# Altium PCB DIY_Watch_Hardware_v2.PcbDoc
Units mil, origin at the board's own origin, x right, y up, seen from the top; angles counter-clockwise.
Board outline 2125.98 x 1181.1 mil, 2 copper layers (Top Layer, Bottom Layer); 60 components, 43 nets, 258 pads, 23 vias.
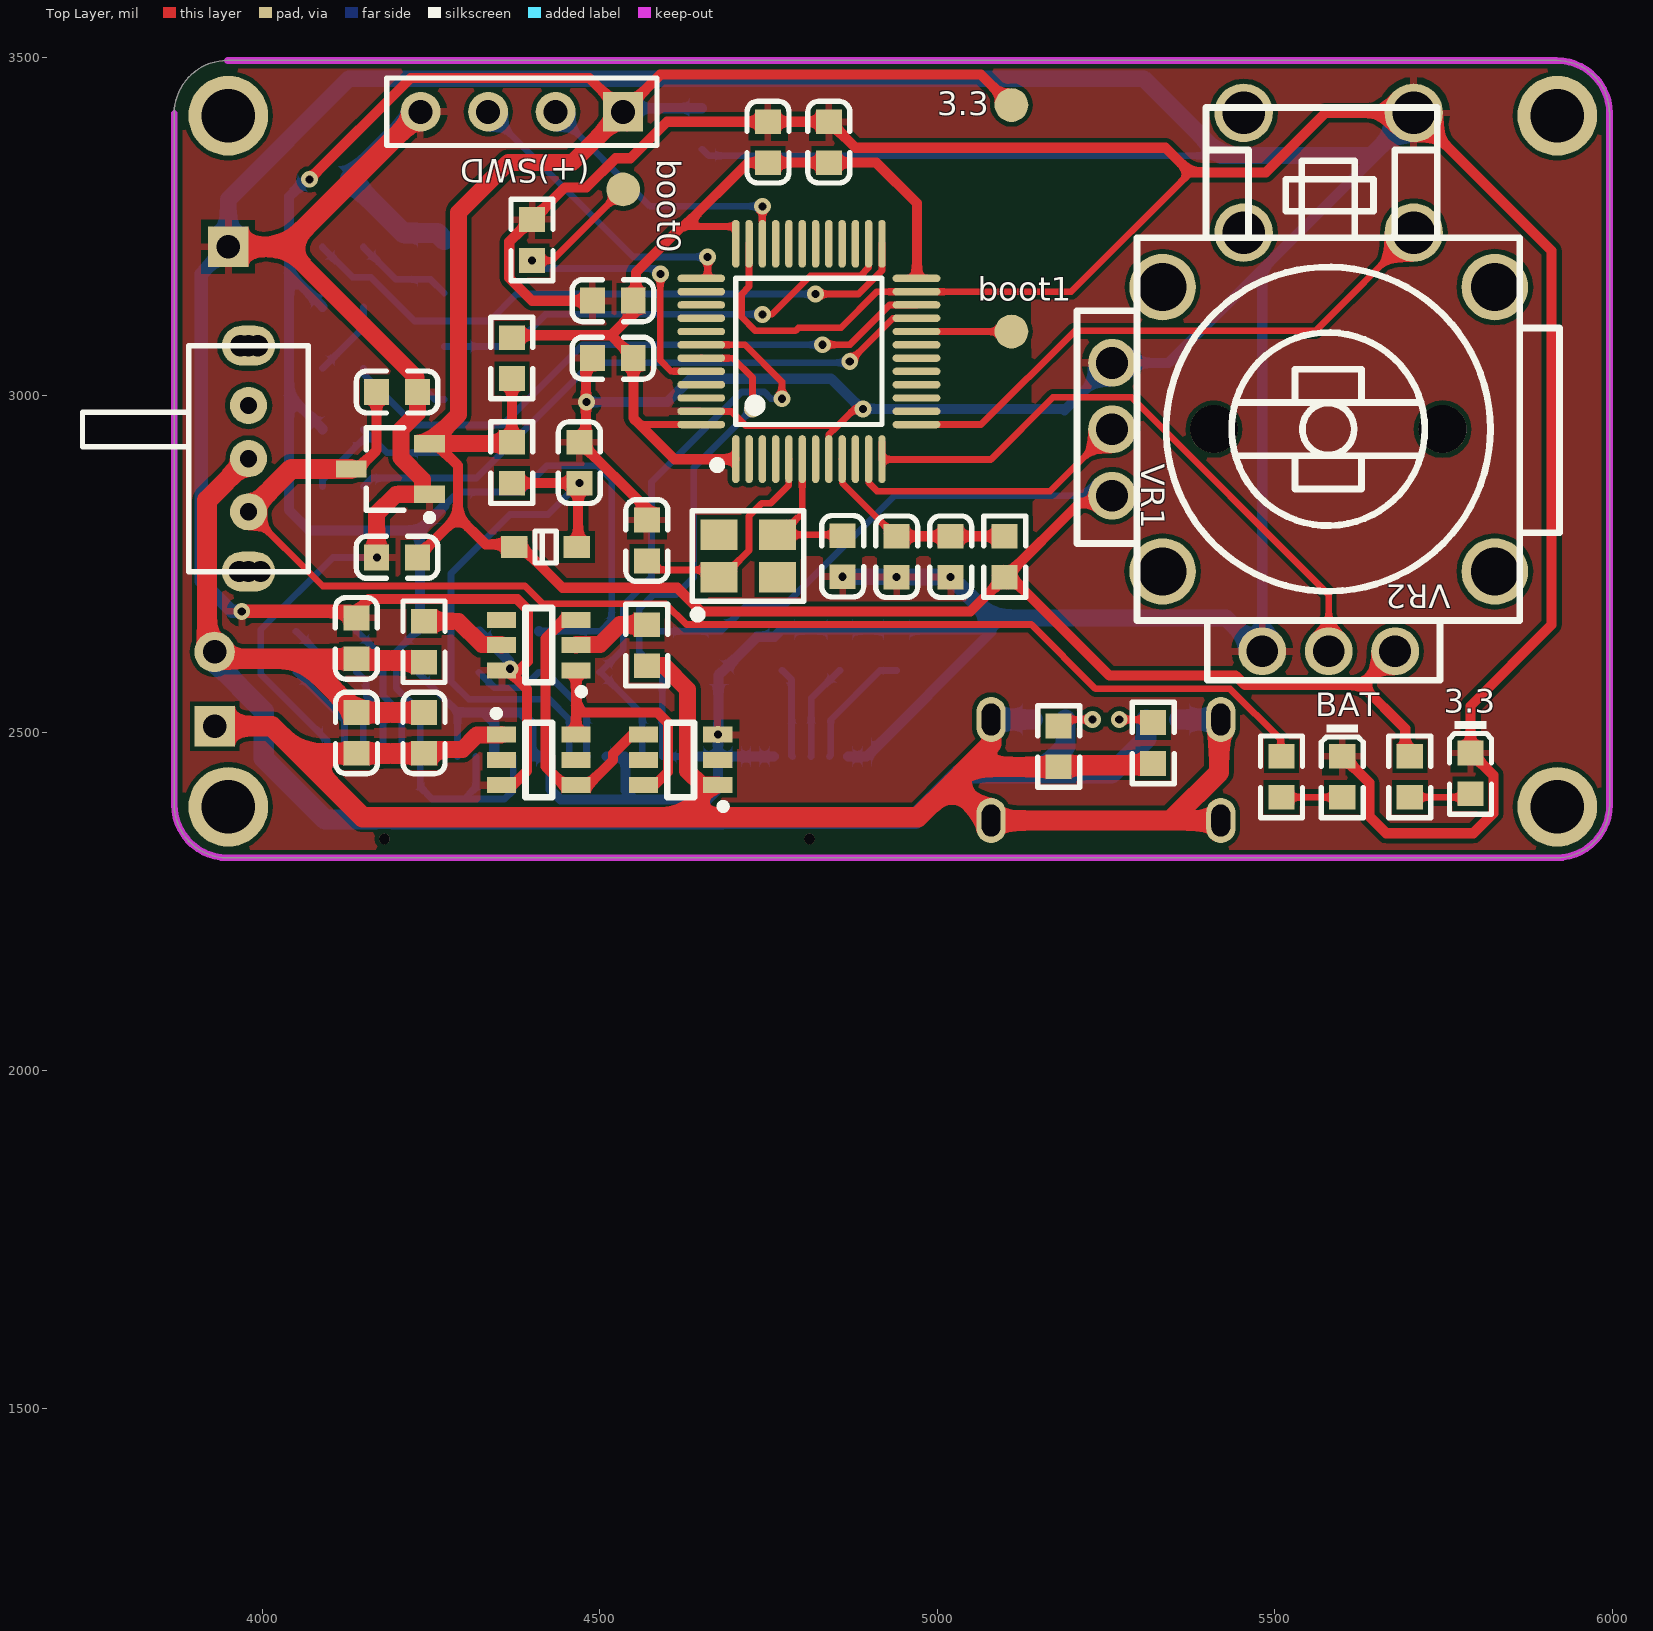
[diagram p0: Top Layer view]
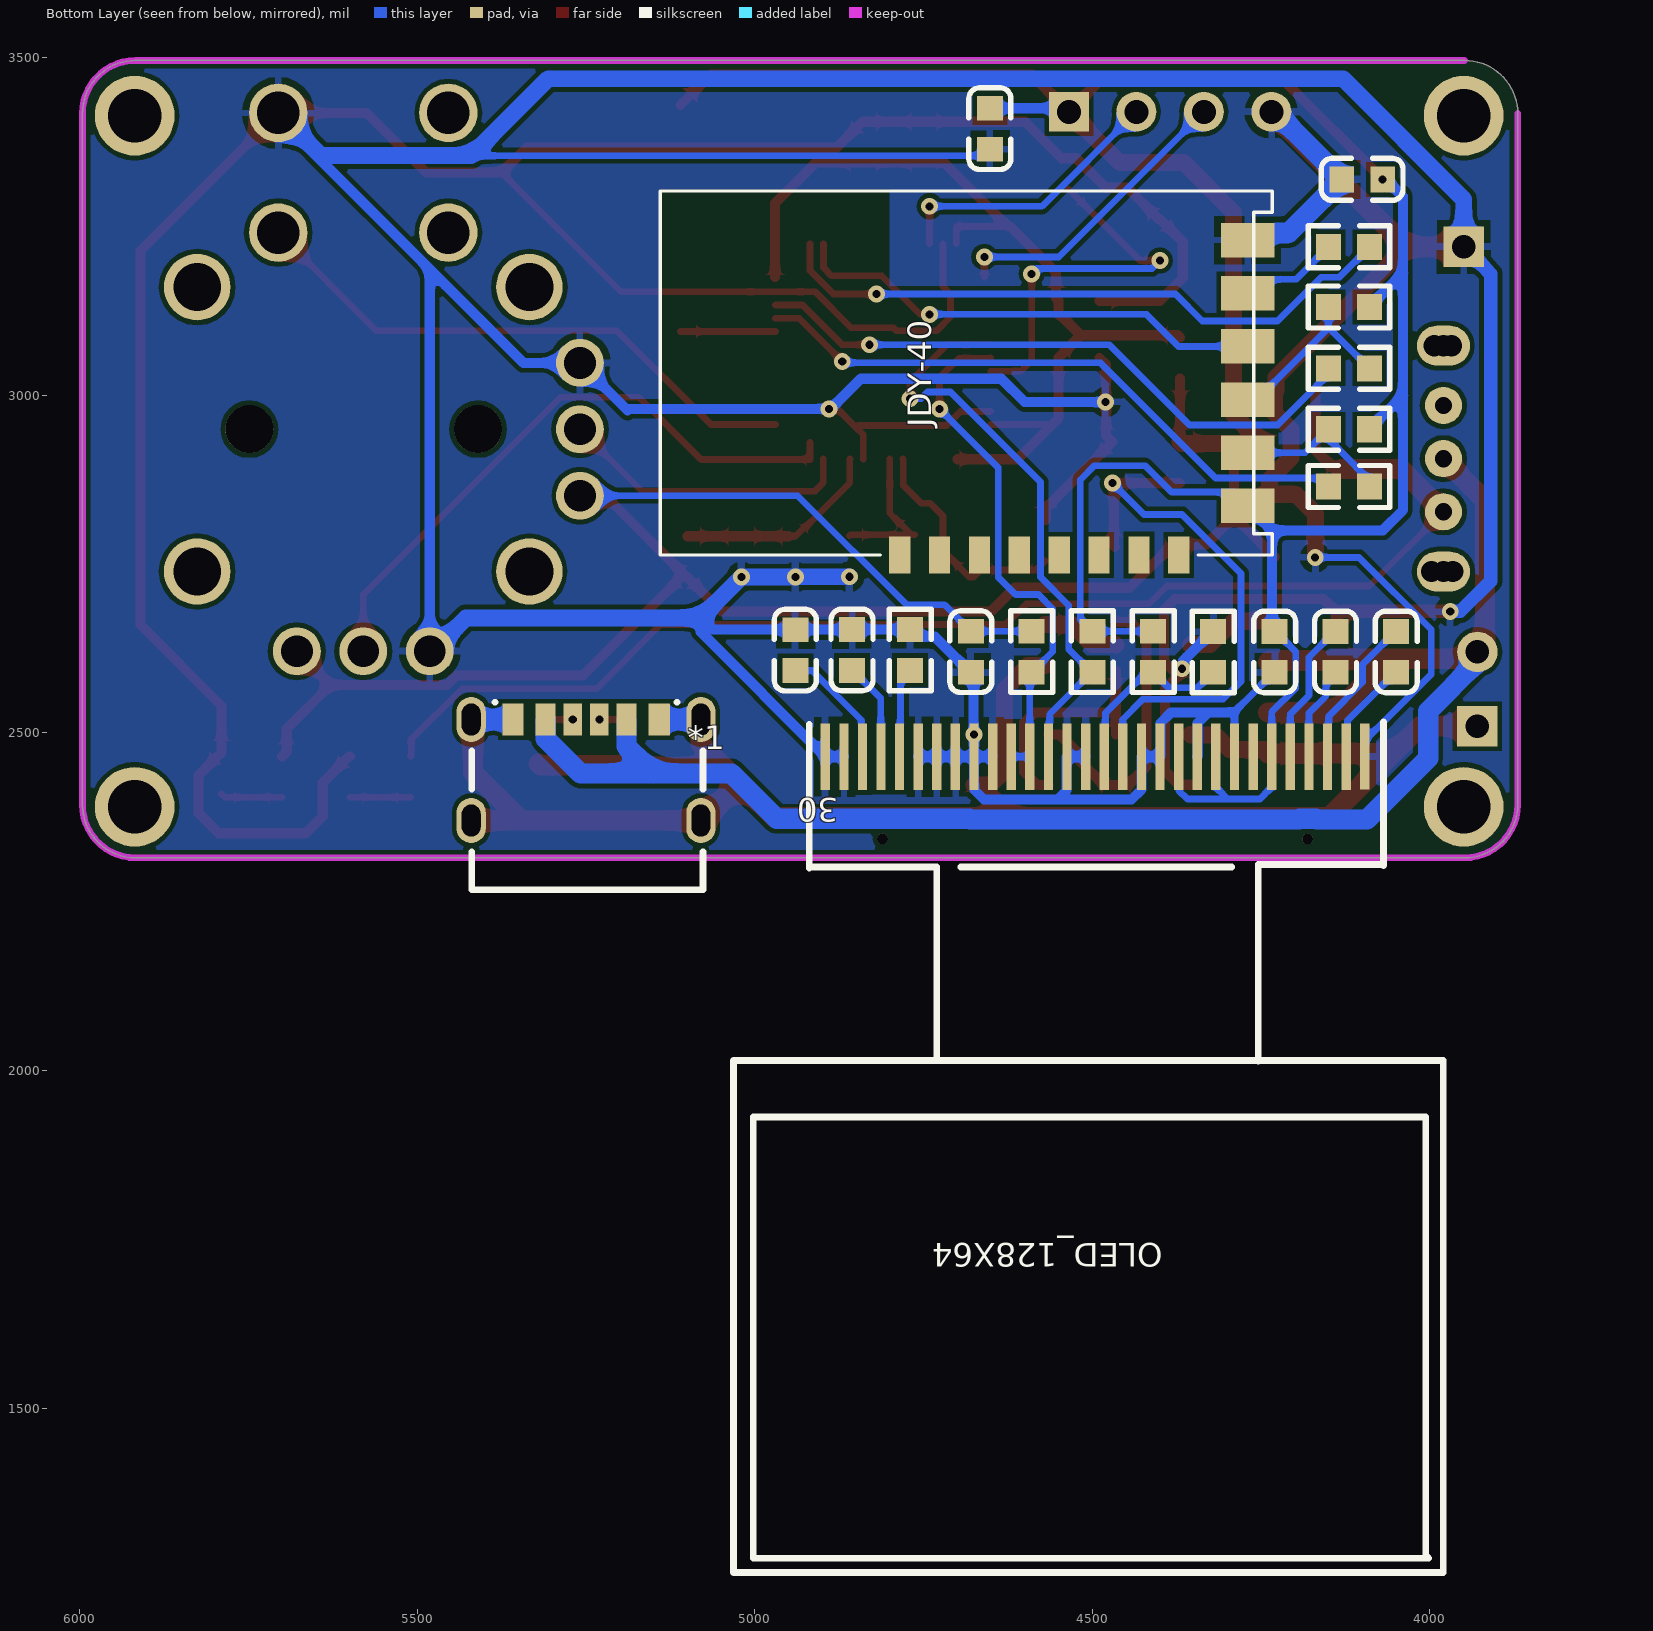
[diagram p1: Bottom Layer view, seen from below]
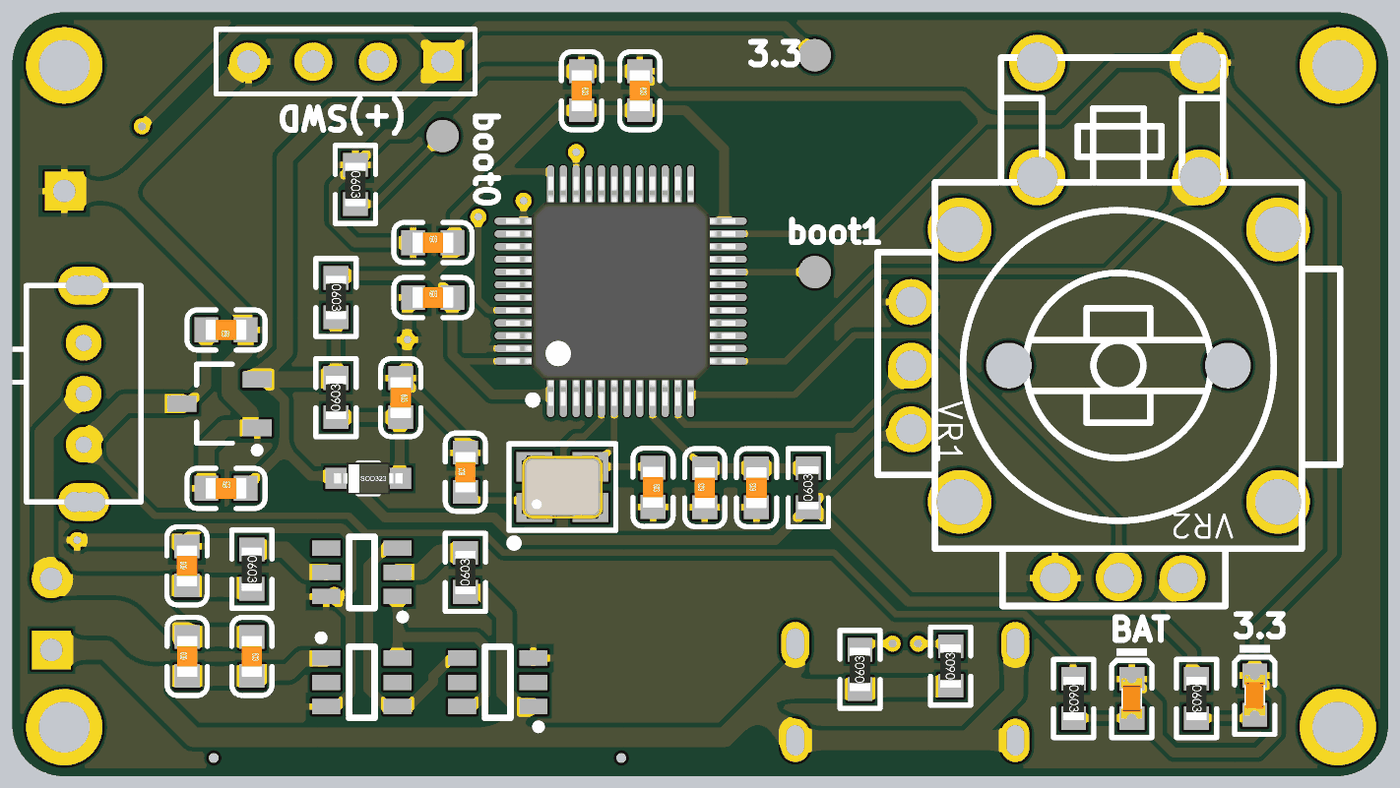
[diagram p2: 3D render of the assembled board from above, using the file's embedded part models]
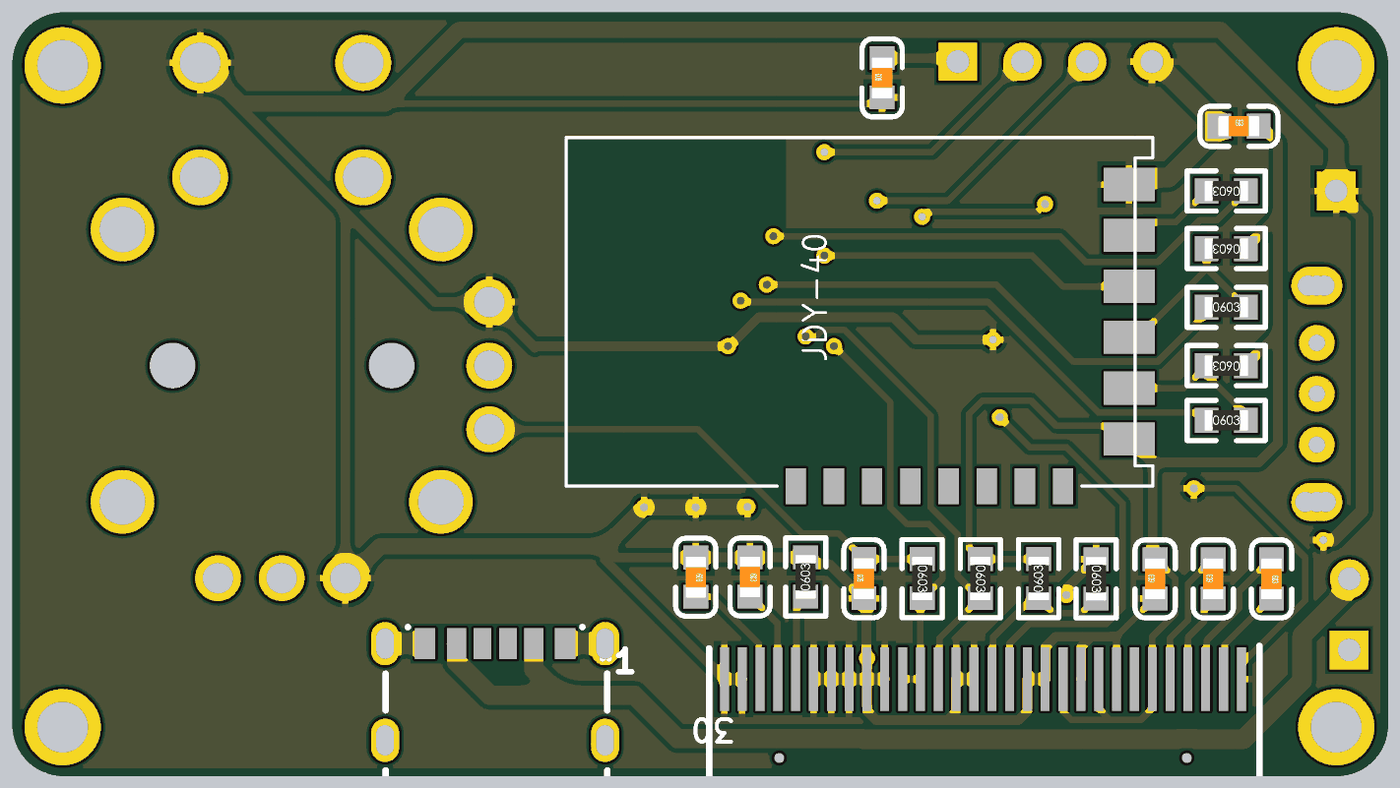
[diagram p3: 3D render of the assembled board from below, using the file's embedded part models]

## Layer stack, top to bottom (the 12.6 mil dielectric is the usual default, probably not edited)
Top Solder: solder mask 0.4, Solder Resist, Dk 3.5
Top Layer: signal copper 1.4
Dielectric 1: dielectric 12.6, FR-4, Dk 4.8
Bottom Layer: signal copper 1.4
Bottom Solder: solder mask 0.4, Solder Resist, Dk 3.5

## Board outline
3870,2393.74 3870,3417.36 cw(c3948.74,3417.36) 3948.74,3496.1 5917.24,3496.1 cw(c5917.24,3417.36) 5995.98,3417.36 5995.98,2393.74 cw(c5917.24,2393.74) 5917.24,2315 3948.74,2315 cw(c3948.74,2393.74)

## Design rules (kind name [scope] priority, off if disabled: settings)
Clearance [All] p1: gap=7 ignorepadtopadclearanceinfootprint=FALSE
MinimumSolderMaskSliver [All] p1: minsoldermaskwidth=0
PolygonConnect [All] p1: connectstyle=Relief reliefconductorwidth=10 reliefentries=4 polygonreliefangle="90 Angle" airgapwidth=10
RoutingVias [All] p1: holewidth=12 width=25 viastyle="Through Hole" minholewidth=12 minwidth=25 maxholewidth=25 maxwidth=50
SilkToSilkClearance [All] p1: silktosilkclearance=0
SilkToSolderMaskClearance [IsPad] p1: minsilkscreentomaskgap=0 clearancetoexposedcopper=TRUE
SolderMaskExpansion [All] p1: expansion=4
Width [All] p1: maxlimit=100 minlimit=7 preferedwidth=10
27 further rules are at their usual default settings.

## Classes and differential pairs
component class DIY_Watch_Hardware: *1

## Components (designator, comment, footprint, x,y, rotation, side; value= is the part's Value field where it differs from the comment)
3.3 "TestPoint" TestPoint 5110,3430 r180 top (schematic designator TP4)
3.3 "红灯 0603" LC-0603_LED_S1 5790,2440 r270 top (schematic designator D2)
(+)SWD "Header 4" HDR1X4 4534.88,3420 r180 top (schematic designator SWD)
*1 "OLED_30Pin" OLED_0.96-30P-P0.70-12864 4495.98,2464.99 r0 bottom
BAT "红灯 0603" LC-0603_LED_S1 5600,2435 r270 top (schematic designator D3)
boot0 "TestPoint" TestPoint 4534.88,3305 r90 top (schematic designator TP1)
boot1 "TestPoint" TestPoint 5110,3094.53 r90 top (schematic designator TP7)
C2 "1uF/0603/50V" LC-0603_C 4050,2620 r270 bottom
C3 "1uF/0603/50V" LC-0603_C 4140,2620 r90 bottom
C4 "22pF/0603/50V" LC-0603_C 4570,2785 r90 top
C5 "22pF/0603/50V" LC-0603_C 4860,2761.65 r270 top
C6 "100nF/0603/50V" LC-0603_C 4519.69,3055.16 r0 top
C7 "100nF/0603/50V" LC-0603_C 4749.53,3375 r270 top
C8 "100nF/0603/50V" LC-0603_C 4519.69,3140.16 r0 top
C9 "100nF/0603/50V" LC-0603_C 4839.53,3375 r270 top
C10 "2.2uF/0603/16V" LC-0603_C 4940,2622.6 r270 bottom
C11 "4.7uF/0603/16V" LC-0603_C 4856.06,2622.91 r270 bottom
C12 "100nF/0603/50V" LC-0603_C 5020,2760.98 r90 top
C13 "1uF/0603/50V" LC-0603_C 4940,2760.98 r90 top
C14 "100nF/0603/50V" LC-0603_C 4139.69,2640 r90 top
C15 "1uF/0603/50V" LC-0603_C 4200,3005 r180 top
C16 "1uF/0603/50V" LC-0603_C 4200,2760 r0 top
C17 "10uF/0603/10V" LC-0603_C 4470,2900.32 r270 top
C18 "1uF/0603/50V" LC-0603_C 4680,2620.32 r90 bottom
C19 "1uF/0603/50V" LC-0603_C 4230,2620 r90 bottom
C20 "100nF/0603/50V" LC-0603_C 4100.43,3320 r180 bottom
C21 "100nF/0603/50V" LC-0603_C 4240,2500 r270 top
C22 "1uF/0603/50V" LC-0603_C 4140,2500 r90 top
C23 "104" LC-0603_C 4651.81,3395 r90 bottom
CiZhu1 "600R/0603/5%" 0603_R 5100,2760.98 r90 top value=?
D1 "1N4148WS T4" LC-SOD-323 4420,2775.32 r0 top
R1 "5.1kΩ/0603/1%" LC-0603_R 5320,2485 r90 top
R2 "10KΩ/0603/1%" LC-0603_R 4400,3230 r270 top
R3 "4.7KΩ/0603/1%" LC-0603_R 4410,2620.31 r90 bottom
R4 "4.7KΩ/0603/1%" LC-0603_R 4321.1,2620 r270 bottom
R5 "4.7KΩ/0603/1%" LC-0603_R 4500,2620.32 r270 bottom
R6 "4.7KΩ/0603/1%" LC-0603_R 4590,2620.32 r270 bottom
R7 "0Ω/0603/1%" LC-0603_R 4370,3055.16 r270 top
R8 "1KΩ/0603/1%" LC-0603_R 4570,2630 r90 top
R9 "100Ω/0603/1%" LC-0603_R 4240,2635 r270 top
R10 "5.1kΩ/0603/1%" LC-0603_R 5180,2480 r90 top
R11 "4.7KΩ/0603/1%" LC-0603_R 4120,2949.74 r0 bottom
R13 "4.7KΩ/0603/1%" LC-0603_R 4120,3130.87 r0 bottom
R14 "4.7KΩ/0603/1%" LC-0603_R 4370,2900.32 r90 top
R15 "100Ω/0603/1%" LC-0603_R 4120,2865 r180 bottom
R16 "100Ω/0603/1%" LC-0603_R 4120,3040 r180 bottom
R17 "100Ω/0603/1%" LC-0603_R 4120,3220 r0 bottom
R18 "1MΩ/0603/1%" LC-0603_R 4770,2622.91 r90 bottom
R19 "1KΩ/0603/1%" LC-0603_R 5700,2435 r270 top
R20 "1KΩ/0603/1%" LC-0603_R 5510,2435 r270 top
S "SW-SPDT" 8.5*3.5_3P 3981.97,2906.26 r270 top
SW1 "RKJXV1224005" RKJXV1224005 5579.94,2949.74 r180 top
U1 "STM32F103C8T6" LQFP-48_7x7x05P 4810,3065 r0 top
U2 "DW01KA" SOT-23-6 4410,2630 r0 top
U3 "SC8205C" SOT-23-6 4410,2460 r180 top
U4 "SC8205C" SOT-23-6 4620,2460 r0 top
U5 "SC662K-3.3V" SOT-23-3L 4190,2890.98 r0 top
USB1 "TYPE-C 6P" TYPE-C-SMD_TYPE-C-6P 5250,2445 r180 bottom
X1 "无源贴片晶振" SMD-3225_4P 4720,2761.97 r0 top
Y1 "JDY-40_1" "JDY-401 -No via" 4785.42,2763.43 r90 bottom

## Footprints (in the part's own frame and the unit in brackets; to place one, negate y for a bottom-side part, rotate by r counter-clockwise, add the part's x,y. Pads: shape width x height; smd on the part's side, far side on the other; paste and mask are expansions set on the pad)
8.5*3.5_3P [mm]
  round 1.4 hole 0.65: 1(2,-0.05) 2(0,-0.05) 3(-2,-0.05)
  oval 1.5x2 hole 0.8: 4(-4.25,-0.05) 5(4.25,-0.05)
  round 0.8 hole 0.8: 18(-4.25,0.3) 19(-4.25,-0.35) 20(4.25,0.4) 21(4.25,-0.4)
  silkscreen extent -4.25,-6.3 4.25,2.2
0603_R [mm]
  rect 0.93x0.98 smd: 1(-0.77,0) 2(0.77,0)
  silkscreen extent -1.53,-0.79 1.54,0.79, body extent -0.85,-0.4 0.85,0.4, height 0.56
HDR1X4 [mm] "Connector; Header; 4 Position"
  rect 1.5x1.5 hole 0.9: 1(0,0)
  round 1.5 hole 0.9: 2(2.54,0) 3(5.08,0) 4(7.62,0)
  silkscreen extent -1.27,-1.27 8.89,1.27
"JDY-401 -No via" [mm] "串口透传"
  rect 1.4x0.8 smd: 1(0,0) 2(0,-1.5) 3(0,-3) 4(0,-4.5) 5(0,-6) 6(0,-7.5) 7(0,-9) 8(0,-10.5)
  rect 1.3x2 smd: 9(1.85,-13.092) 10(3.85,-13.092) 11(5.85,-13.092) 12(7.85,-13.092) 13(9.85,-13.092) 14(11.85,-13.092)
  silkscreen extent 0,-14.02 13.7,9.01
LC-0603_C [mm]
  rect 0.93x0.98 smd: 1(-0.77,0) 2(0.77,0)
  silkscreen extent -1.53,-0.79 1.54,0.79, body extent -0.8,-0.4 0.8,0.4, height 0.3
LC-0603_LED_S1 [mm]
  rect 0.93x0.98 smd: A(0.77,0) K(-0.77,0)
  silkscreen extent -1.98,-0.79 1.54,0.79, body extent -0.8,-0.4 0.8,0.4, height 0.6
LC-0603_R [mm]
  rect 0.93x0.98 smd: 1(-0.77,0) 2(0.77,0)
  silkscreen extent -1.53,-0.79 1.54,0.79, body extent -0.85,-0.4 0.85,0.4, height 0.56
LC-SOD-323 [mm]
  rect 1x0.83 smd: 1(1.18,0) 2(-1.18,0)
  silkscreen extent -0.4,-0.6 0.4,0.6, body extent -1.35,-0.62 1.35,0.62, height 1.1
LQFP-48_7x7x05P [mm]
  oval 0.28x1.8 smd mask+0.051: 1(-2.75,-4.05) 2(-2.25,-4.05) 3(-1.75,-4.05) 4(-1.25,-4.05) 5(-0.75,-4.05) 6(-0.25,-4.05) 7(0.25,-4.05) 8(0.75,-4.05) 9(1.25,-4.05) 10(1.75,-4.05) 11(2.25,-4.05) 12(2.75,-4.05) 25(2.75,4.05) 26(2.25,4.05) 27(1.75,4.05) 28(1.25,4.05) 29(0.75,4.05) 30(0.25,4.05) 31(-0.25,4.05) 32(-0.75,4.05) 33(-1.25,4.05) 34(-1.75,4.05) 35(-2.25,4.05) 36(-2.75,4.05)
  oval 1.8x0.28 smd mask+0.051: 13(4.05,-2.75) 14(4.05,-2.25) 15(4.05,-1.75) 16(4.05,-1.25) 17(4.05,-0.75) 18(4.05,-0.25) 19(4.05,0.25) 20(4.05,0.75) 21(4.05,1.25) 22(4.05,1.75) 23(4.05,2.25) 24(4.05,2.75) 37(-4.05,2.75) 38(-4.05,2.25) 39(-4.05,1.75) 40(-4.05,1.25) 41(-4.05,0.75) 42(-4.05,0.25) 43(-4.05,-0.25) 44(-4.05,-0.75) 45(-4.05,-1.25) 46(-4.05,-1.75) 47(-4.05,-2.25) 48(-4.05,-2.75)
  silkscreen extent -3.6,-4.42 2.75,2.75, body extent -4.5,-4.5 4.5,4.5, height 1.6
OLED_0.96-30P-P0.70-12864 [mm]
  rect 0.351x2.499 smd: 1(-10.149,-0.002) 2(-9.444,0) 3(-8.744,0) 4(-8.044,0) 5(-7.344,0) 6(-6.644,0) 7(-5.944,0) 8(-5.244,0) 9(-4.544,0) 10(-3.844,0) 11(-3.144,0) 12(-2.444,0) 13(-1.744,0) 14(-1.044,0) 15(-0.344,0) 16(0.356,0) 17(1.056,0) 18(1.756,0) 19(2.456,0) 20(3.156,0) 21(3.856,0) 22(4.556,0) 23(5.256,0) 24(5.956,0) 25(6.656,0) 26(7.356,0) 27(8.056,0) 28(8.751,0.001) 29(9.45,0.002) 30(10.149,0.002)
  round 0.4 hole 0.4 unplated: ""(-8,3.1) ""(8,3.1)
  silkscreen extent -13.1,-1.3 13.6,30.7
RKJXV1224005 [mm]
  round 1.8 hole 1.2: 1(8.15,-2.5) 2(8.15,0) 3(8.15,2.5) 4(2.5,8.35) 5(0,8.35) 6(-2.5,8.35)
  round 2.5 hole 1.8: 7(-6.25,5.35) 8(-6.25,-5.35) 9(6.25,-5.35) 10(6.25,5.35)
  round 2.2 hole 1.6: a(-3.2,-7.4) b(-3.2,-11.9) c(3.2,-7.4) d(3.2,-11.9)
  round 1.8 hole 1.8 unplated: ""(-4.284,-0.006) ""(4.316,-0.006)
  silkscreen extent -8.68,-12.11 9.47,9.44
SMD-3225_4P [mm] "晶振"
  rect 1.4x1.15 smd: 1(-1.1,-0.8) 2(1.1,-0.8) 3(1.1,0.8) 4(-1.1,0.8)
  silkscreen extent -2.1,-2.35 2.1,1.7, body extent -1.6,-1.25 1.6,1.25, height 0.61
SOT-23-3L [mm] "http://www.aosmd.com/res/packaging_information/SOT-23-3L.pdf"
  rect 1.15x0.65 smd: 1(1.475,-0.95) 2(1.475,0.95) 3(-1.475,0)
  silkscreen extent -0.9,-1.95 1.6,1.55, body extent -0.9,-1.55 0.9,1.55, height 1.25
SOT-23-6 [mm]
  rect 1.1x0.6 smd: 1(1.4,-0.95) 2(1.4,0) 3(1.4,0.95) 4(-1.4,0.95) 5(-1.4,0) 6(-1.4,-0.95)
  silkscreen extent -0.5,-1.87 1.73,1.4
TestPoint [mil]
  round 50 smd: 1(0,0)
TYPE-C-SMD_TYPE-C-6P [mm]
  oval 1.1x1.7 hole 0.7 slot 1.2 at 90 deg: 7(-4.32,-1.9) 7(-4.32,1.9) 7(4.32,-1.9) 7(4.32,1.9)
  rect 0.7x1.2 smd: A5(-0.5,1.9) B5(0.5,1.9)
  rect 0.76x1.2 smd: A9(1.52,1.9) B9(-1.52,1.9)
  rect 0.8x1.2 smd: A12(2.75,1.9) B12(-2.75,1.9)
  silkscreen extent -4.3,-4.5 4.4,2.55

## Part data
3.3 BAT: library part "0603 红灯", "发光二极管", Package=0603, SuppliersPartNumber=C2286
(+)SWD: "Header, 4-Pin"
C2 C3 C13 C15 C16 C18 C19 C22: library part "0603 1uF (105) 10% 50V", "贴片电容", Package=0603, SuppliersPartNumber=C15849
C4 C5: library part "0603 22pF (220) 5% 50V", "贴片电容", Package=0603, SuppliersPartNumber=C1653
C6 C7 C8 C9 C12 C14 C20 C21: library part "0603 100nF (104) 10% 50V", "贴片电容", Package=0603, SuppliersPartNumber=C14663
C10: library part "0603 2.2uF (225) 10% 16V", "贴片电容", Package=0603, SuppliersPartNumber=C23630
C11: library part "0603 4.7uF (475) 10% 16V", "贴片电容", Package=0603, SuppliersPartNumber=C19666
C17: library part "0603 10uF (106) 10% 10V", "贴片电容", Package=0603, SuppliersPartNumber=C19702
C23: library part "Cap Chip 0603", "Polarized Capacitor (Radial)"
CiZhu1: library part Cizhu, "电阻_磁珠"
D1: library part "SOD-323 1N4148WS T4", "二极管", Package=SOD-323, SuppliersPartNumber=C2128
R1 R9 R10 R15 R16 R17: library part "0603 100Ω (1000) 1%", "贴片电阻", Package=0603, SuppliersPartNumber=C22775
R2: library part "0603 10KΩ (1002) 1%", "贴片电阻", Package=0603, SuppliersPartNumber=C25804
R3 R4 R5 R6 R11 R13 R14: library part "0603 4.7KΩ (4701) 1%", "贴片电阻", Package=0603, SuppliersPartNumber=C23162
R7: library part "0603 0Ω (0R0) 1%", "贴片电阻", Package=0603, SuppliersPartNumber=C21189
R8 R19 R20: library part "0603 1KΩ (1001) 1%", "贴片电阻", Package=0603, SuppliersPartNumber=C21190
R18: library part "0603 1MΩ (1004) 1%", "贴片电阻", Package=0603, SuppliersPartNumber=C22935
S: "SPDT Subminiature Toggle Switch, Right Angle Mounting, Vertical Actuation"
SW1: BOM_JLCPCB Part Class="Extended Part", BOM_Manufacturer="ALPS Electric"
U1: "ARM", Package=LQFP-48_7x7x05P, SuppliersPartNumber=C8734
U2: "锂电池保护芯片"
U3 U4: "二合一MOS"
U5: "LDO"
USB1: BOM_JLCPCB Part Class="Extended Part", BOM_Manufacturer="SHOU HAN"
X1: library part XTAL_4, "25M/3225"
Y1: "串口透传无过孔"

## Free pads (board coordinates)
  round 60 hole 35: 4(3929.68,2620)
  rect 60x60 hole 35: 5(3930,2510) 6(3950,3220)
  round 118.11 hole 78.74: 7(3950,2390.55) 7(3950,3414.17) 7(5918.5,2390.55) 7(5918.5,3414.17)

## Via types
v1: diameter 25, hole 12, Top Layer to Bottom Layer, 23 vias

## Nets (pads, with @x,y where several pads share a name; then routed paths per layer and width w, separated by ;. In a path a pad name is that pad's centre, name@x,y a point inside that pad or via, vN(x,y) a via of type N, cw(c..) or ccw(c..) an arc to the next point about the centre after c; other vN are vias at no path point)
3V3: 3.3.1 (+)SWD.1 *1.6 *1.9 *1.11 C16.2 C18.2 C19.2 C20.2 C23.2 CiZhu1.1 D1.2 R3.2 R5.1 R6.1 R7.2 R11.1 R13.1 R14.2 R19.1 SW1.3 SW1.6 U5.2 Y1.9 | length 7207.6
  Top Layer w15: v1(4070.11,3320) 4220.11,3470 4484.88,3470 4534.88,3420 4589.88,3475 5065,3475 3.3.1 ; C16.2 4230.31,2760.98 4290,2820.67 ; U5.2@4257.91,2928.39 4290,2896.3 4290,2820.67 ; R14.2 R7.2 ; SW1.3 5248.38,2840.63 5210.95,2840.63 CiZhu1.1@5100.98,2730.67 ; SW1.6 5628.43,2571.07 ; R19.1 5693.38,2471.94 5693.38,2506.12 5628.43,2571.07 ; 4290,2820.67 4331.36,2779.31 4369.55,2779.31 D1.2 4384.69,2775.32 4445,2715 4615,2715 4650,2680 5049.33,2680 CiZhu1.1 CiZhu1.1@5100.98,2730.67 ; CiZhu1.1@5100.98,2730.67 5109.33,2730.67 5255.23,2584.77 5442.1,2584.77 5455.79,2571.07 5628.43,2571.07
  Top Layer w25: U5.2 4257.91,2928.39 U5.2@4258.21,2928.68 ; R14.2 4368.05,2928.68 U5.2@4258.21,2928.68 ; 4534.88,3420 4459.57,3344.68 4364.69,3344.68 4290.98,3270.98 4290.98,2971.3 4258.21,2938.52 U5.2@4258.21,2928.68
  Bottom Layer w10: C19.2@4229.02,2650.32 4198.71,2620.01 4198.71,2566.41 4234.41,2530.71 *1.6 4234.41,2419.49 4251.9,2402 4299.59,2402 ; Y1.9 4290.59,2856.85 4382.94,2856.85 4421.94,2895.86 4497.03,2895.86 4517.89,2875 4517.89,2667.54 4500.98,2650.63 R5.1 R3.2 ; *1.9 4317.08,2419.49 4299.59,2402 ; *1.11 4372.2,2414.93 4359.27,2402 4299.59,2402 ; R6.1 C18.2 4719.37,2690 4775.55,2690 4936.87,2851.32 SW1.3
  Bottom Layer w15: v1(4070.11,3320) 4065.43,3320 4040,3294.57 4040,3181.54 ; R11.1 4089.69,2950.73 4040,3000.41 ; R13.1 4089.69,3131.85 4040,3181.54 ; C19.2@4229.02,2650.32 4233.74,2655.04 4233.74,2800 ; Y1.9 4233.74,2800 ; 4534.88,3420 4540.2,3425.32 C23.2 ; 4040,3000.41 4040,3181.54 ; 4040,3000.41 4040,2830 4070,2800 4233.74,2800
BAT: C14.1 C21.1 C22.2 pad.4 R9.2 S.2 USB1.A9 USB1.B9 | length 2556.1
  Top Layer w30: S.2@3976.26,2910 3976.26,2902.52 3918.63,2844.89 3918.63,2631.05 pad.4 3937.8,2620 3948.12,2609.68 4059.65,2609.68 ; C21.1 C22.2 4139.02,2530.32 4059.65,2609.68 ; R9.2 4237.5,2607.18 4142.19,2607.18 C14.1 4059.65,2609.68
  Bottom Layer w30: pad.4 3929.68,2605.32 4002.71,2532.29 4002.71,2462.29 4093.2,2371.8 4167.63,2371.8 4168.65,2372.81 4193.39,2372.81 4194.41,2371.8 4681.27,2371.8 4682.28,2372.81 4967.81,2372.81 5035,2440 5150,2440 ; USB1.A9 5190.12,2519.77 5190.12,2480.12 5150,2440 ; USB1.B9 USB1.B9 5309.8,2491.41 5258.39,2440 5150,2440
BAT+: C15.2 R20.1 S.1 U5.3 | length 2008.3
  Top Layer w10: S.1 4089.9,2717.62 4389.6,2717.62 4416.01,2691.21 4597.84,2691.21 4628.56,2660.5 5139.5,2660.5 5234.73,2565.27 5434.02,2565.27 5509.02,2490.27 5509.02,2465.31 R20.1
  Top Layer w15: U5.3 4141.77,2890.98 4169.69,2918.9 C15.2
  Top Layer w30: S.1 4043.46,2890.98 U5.3
BOOT0: boot0.1 R2.2 U1.44 | length 572.3
  Top Layer w10: v1(4400,3199.68) 4429.57,3199.68 boot0.1 ; v1(4590,3180) 4590,3051.53 4605.86,3035.67 4650.36,3035.67 U1.44
  Bottom Layer w10: v1(4400,3199.68) 4411.68,3188 4582,3188 v1(4590,3180)
BOOT1: boot1.1 U1.20 | length 140.6
  Top Layer w10: U1.20 boot1.1
CS: R17.1 U1.25 | length 945.2
  Top Layer w10: v1(4820,3150) 4883.39,3150 4918.27,3184.88 U1.25
  Bottom Layer w10: R17.1 4089.69,3219.02 4133.7,3175 4160.75,3175 4225.68,3110.07 4337.25,3110.07 4377.18,3150 v1(4820,3150)
GND: 3.3.K (+)SWD.4 *1.1 *1.8 *1.10 *1.12 *1.13 *1.16 *1.17 *1.21 *1.22 *1.23 *1.24 *1.25 *1.29 *1.30 BAT.K C4.2 C5.2 C6.1 C7.1 C8.1 C9.1 C10.1 C11.1 C12.1 C13.1 C14.2 C15.1 C16.1 C17.1 C18.1 C19.1 C20.1 C23.1 pad.6 R2.1 R4.1 R18.2 SW1.1 SW1.4 SW1.b U1.8 U1.23 U1.35 U1.47 U2.6 U3.3 U4.3 U5.1 Y1.14 | length 15123.5
  Top Layer w10: U1.47 4650.75,2976.22 4695.49,2976.22 4716.21,2955.5 4846.8,2955.5 4850,2952.3 ; U1.35 4721.42,3161.06 4710,3149.64 4710,3116.45 4730.95,3095.5 4789.9,3095.5 4794.51,3100.12 4857.55,3100.12 4911.01,3153.58 U1.23 5198.58,3153.58 5375,3330 ; U1.8 4839.33,2905.75 4839.33,2941.63 4850,2952.3 ; v1(4890,2980) 4877.7,2980 4850,2952.3
  Top Layer w15: C14.2@4130,2680 C14.2 4139.69,2680.33 4157.47,2698.12 4378.13,2698.12 4393.7,2682.56 4393.7,2605.7 4380.6,2592.6 ; U3.3 4355.57,2423.29 4372.14,2423.29 4392.22,2443.37 4392.22,2565.1 U2.6@4364.79,2592.53 ; C6.1 4479.69,3045.47 4479.69,2940.32 C17.1 4470.98,2930.63 4569.02,2832.6 4569.02,2815.32 C4.2 ; C8.1 4399.84,3140.16 4366.21,3173.79 4366.21,3227.51 4399.02,3260.31 R2.1 4400.98,3260.31 4448.57,3307.9 4480.41,3307.9 4523.71,3351.21 4545.65,3351.21 4599.76,3405.32 C7.1 C9.1 4840.51,3405.32 4879.07,3366.76 5338.24,3366.76 5375,3330 5486.65,3330 5574.89,3418.25 SW1.b 5910,3214.17 5910,2660 5790,2540 3.3.K 5790.98,2470.31 5823.79,2437.51 5823.79,2380.89 5794.23,2351.33 5665,2351.33 5640,2376.33 5640,2426.3 5600.98,2465.31 BAT.K
  Top Layer w20: v1(3970,2680) C14.2@4130,2680
  Top Layer w25: 4034.88,3220 4228.21,3026.67 4228.21,3007.11 C15.1 4230.31,2973.64 4205.93,2949.26 4205.93,2907.51 4237.93,2875.51 4237.93,2853.88 4238.23,2853.58 U5.1 4247.78,2853.29 4198.4,2853.29 4169.69,2824.57 C16.1
  Top Layer w30: pad.6 4034.88,3220 4234.88,3420
  Bottom Layer w10: *1.1 4096.41,2488.71 3997.92,2587.19 3997.92,2652.81 4105.12,2760 v1(4170,2760) ; C19.1 4230.98,2589.68 4289.52,2531.15 *1.8 ; C23.1 4661.49,3355 5420,3355
  Bottom Layer w15: 4289.52,2531.15 4297.49,2531.15 4298.14,2530.5 4328.19,2530.5 ; R4.1 4322.08,2650.31 4365.35,2607.05 4365.35,2596.91 v1(4367.27,2595) ; *1.10 4344.04,2465.6 4344.04,2514.65 4328.19,2530.5 ; v1(4480.54,2990) 4600.41,2990 4634.91,3024.5 4842.96,3024.5 4887.46,2980 v1(4890,2980) 5185.91,2980 5188.41,2977.51 SW1.1 5342.79,3048.17 5481.51,3186.89 ; *1.16 *1.17 4538.16,2464.4 4538.16,2414.47 4551.34,2401.3 ; *1.21 *1.22 ; *1.25 *1.24 *1.23 *1.22 ; *1.29 *1.30 5080.27,2649.62 5080.27,2670.4 5062.78,2652.91 C10.1 4939.84,2653.07 4856.22,2653.07 C11.1 R18.2 4759.19,2642.42 4733.41,2642.42 4680.98,2590 C18.1 4675.95,2585.95 4675.95,2506.7 4675.35,2506.1 *1.22 ; SW1.4 5481.51,3186.89 ; SW1.b 5705.92,3411.3 5481.51,3186.89 ; 4328.19,2530.5 4383.31,2530.5 4399.16,2514.65 4399.16,2465.6 *1.12 *1.13 4427.32,2415.95 4441.97,2401.3 4551.34,2401.3 ; 4551.34,2401.3 4660.7,2401.3 4674.75,2415.35 4674.75,2423.3 4675.35,2423.9 *1.22
  Bottom Layer w20: pad.6 3910,3180 3910,2725 3955,2680 v1(3970,2680)
  Bottom Layer w25: pad.6 3950,3290 4129.03,3469.03 5305.97,3469.03 5420,3355 5642.67,3355 SW1.b ; v1(4860,2731.34) 4939.33,2731.34 v1(4940,2730.67) v1(5020,2730.67) 5080.27,2670.4 5427.76,2670.4 5477.16,2621 SW1.4
  Bottom Layer w30: 4234.88,3420 4229.76,3420 4130.74,3320.98 C20.1 4130.74,3319.02 4209.21,3240.55 4259.41,3240.55 Y1.14
  other v1: 4675.12,2497.4
Net*1_2: *1.2 C2.2 | length 156
  Bottom Layer w10: C2.2 4050.98,2589.68 4122.27,2518.4 4122.27,2466.9 *1.2
Net*1_3: *1.3 C2.1 | length 228.5
  Bottom Layer w10: C2.1 4050.98,2650.32 4100,2601.3 4100,2575 4149.83,2525.17 4149.83,2468.21 *1.3@4152.97,2465.07
Net*1_4: *1.4 C3.1 | length 141.5
  Bottom Layer w10: C3.1 4140.98,2589.68 4154.29,2576.38 4154.29,2554.34 4179.29,2529.34 *1.4
Net*1_5: *1.5 C3.2 | length 214
  Bottom Layer w10: C3.2 4140.98,2650.32 4179.29,2612.01 4179.29,2555.71 4206.85,2528.15 4206.85,2466.31 *1.5@4208.09,2465.07
Net*1_15: *1.15 R3.1 R4.2 | length 268.7
  Bottom Layer w10: R4.2 4343.78,2567 4387,2567 R3.1 4420,2590 4480.54,2529.46 4480.54,2466.9 *1.15
Net*1_26: *1.26 R18.1 | length 134.6
  Bottom Layer w10: R18.1 4770.98,2592.6 4784.29,2579.29 4784.29,2466.3 *1.26
Net*1_27: *1.27 C11.2 | length 145.9
  Bottom Layer w10: *1.27 4813.36,2465.21 4813.36,2550.89 4855.08,2592.6 C11.2
Net*1_28: *1.28 C10.2 | length 183
  Bottom Layer w10: *1.28 4842.41,2466.84 4842.41,2519.38 4915.31,2592.28 C10.2
NetC4_1: C4.1 U1.5 X1.1 | length 345.4
  Top Layer w10: C4.1 4583.31,2741.38 4665.79,2741.38 X1.1 4681.61,2730.47 4721.42,2770.28 4721.42,2821.42 4740,2840 4753.23,2840 4780.28,2867.05 4780.28,2905.36 U1.5
NetC5_1: C5.1 U1.6 X1.3 | length 222.6
  Top Layer w10: X1.3 X1.3@4768.23,2793.46 ; U1.6 4800.16,2825.39 X1.3@4768.23,2793.46 ; C5.1 4858.5,2793.46 X1.3@4768.23,2793.46
NetD2_A: 3.3.A R19.2 | length 92.1
  Top Layer w10: R19.2 5785,2404.68 3.3.A
NetD3_A: BAT.A R20.2 | length 90
  Top Layer w10: R20.2 BAT.A
NetR1_2: R1.2 USB1.A5 | length 52.2
  Top Layer w10: v1(5269.69,2519.8) 5315.51,2519.8 R1.2
NetR8_2: R8.2 U2.2 | length 117.4
  Top Layer w25: U2.2 4465.81,2630.69 4500.69,2630.69 4530.32,2660.32 R8.2
NetR9_1: R9.1 U2.5 | length 129.5
  Top Layer w25: R9.1 4290.98,2665.31 4325.61,2630.69 4354.19,2630.69 U2.5
NetR10_2: R10.2 USB1.B5 | length 54.2
  Top Layer w10: R10.2 5189.49,2519.8 v1(5230.31,2519.8)
NetR11_2: R11.2 R15.2 Y1.10 | length 249.6
  Bottom Layer w10: R15.2 4089.68,2874.68 4157.11,2942.11 4150.32,2948.9 R11.2 4185.06,2915 Y1.10
NetR13_2: R13.2 R16.2 Y1.11 | length 280.5
  Bottom Layer w10: R16.2 4150.32,3100.63 ; R13.2 4150.32,3100.63 ; Y1.11 4256.22,2993.74 4150.32,3099.65 4150.32,3100.63
NetR17_2: R17.2 Y1.13 | length 148.8
  Bottom Layer w10: R17.2 4150.32,3219.02 4163.62,3205.71 4164.61,3205.71 4198.5,3171.81 4249.41,3171.81 Y1.13
OC: U2.3 U3.4 U4.4 | length 439
  Top Layer w15: U2.3 4461.82,2664.1 4444.1,2664.1 4420,2640 4420,2450 4447.4,2422.6 U3.4 4482.6,2422.6 4520,2460 4520,2469.09 4548.31,2497.4 U4.4
OD: U2.1 U3.6 U4.6 | length 358.7
  Top Layer w15: U3.6 4465.12,2540 ; U2.1 4465.12,2540 ; U4.6 4581.45,2422.6 4601.04,2442.18 4601.04,2515.22 4586.25,2530 4475.12,2530 4465.12,2540
PA1: SW1.2 U1.11 | length 438.6
  Top Layer w10: U1.11 4898.78,2905.36 4898.78,2870.35 4911.01,2858.12 5167.44,2858.12 SW1.2
PA2: SW1.5 U1.12 | length 929.4
  Top Layer w10: U1.12@4918.27,2905 5079.5,2905 5171.68,2997.18 5287.82,2997.18 5579.94,2705.07 SW1.5 ; U1.12 U1.12@4918.27,2930
PA3: SW1.a U1.13 | length 854.3
  Top Layer w10: U1.13 5065,2956.73 5203.87,3095.6 5560.44,3095.6 SW1.a
PGND: C21.2 C22.1 pad.5 R1.1 R8.1 R10.1 U3.1 U4.1 USB1.7 USB1.A12 USB1.B12 | length 2900.4
  Top Layer w25: C21.2 4245.81,2475.49 4296.79,2475.49 4318.01,2496.71 4354.19,2496.71 U3.1 ; R8.1 4595.31,2599.69 4630.39,2564.61 4630.39,2443.68 4650.79,2423.29 4674.43,2423.29 U4.1 4666.65,2422.6 4619.06,2375
  Top Layer w30: pad.5 4014.35,2510 4054.67,2469.68 ; C21.2 C22.1 4054.67,2469.68 ; USB1.7@5063.08,2384.56 5021.97,2425.66 ; USB1.7@5079.92,2370.2 5350,2370.2 ; USB1.7@5079.92,2519.8 5079.92,2483.61 5046,2449.69 ; R1.1 5317.5,2452.19 5182.5,2452.19 R10.1 5046,2449.69 ; USB1.7@5420.08,2370.2 5350,2370.2 ; USB1.7@5420.08,2519.8 5417.53,2517.26 5417.53,2441.85 5350,2374.31 5350,2370.2 ; 4054.67,2469.68 4149.35,2375 4619.06,2375 4971.31,2375 5021.97,2425.66 ; 5021.97,2425.66 5046,2449.69
  Bottom Layer w30: USB1.7@5079.92,2519.8 USB1.A12 ; USB1.B12 USB1.7@5420.08,2519.8
RES#: *1.14 C17.2 D1.1 R14.1 | length 855
  Top Layer w15: R14.1 v1(4470,2870) 4468.23,2868.23 4468.23,2777.09 D1.1
  Bottom Layer w10: *1.14 4454.88,2520.29 4425.17,2550 4306.22,2550 4280,2576.22 4280,2736.3 4367.27,2823.57 4423.56,2823.57 v1(4470,2870)
RESET: U1.7
SCL: *1.18 R5.2 U1.42 | length 885.4
  Top Layer w10: U1.42 4650.71,3075 4715,3075 4770,3020 v1(4770,2995)
  Bottom Layer w10: R5.2 R5.2@4500.98,2590 ; *1.18 4563.21,2466.9 4563.21,2527.77 R5.2@4500.98,2590 ; v1(4770,2995) 4754,2995 4744,3005 4710.23,3005 4576.94,2871.71 4576.94,2730.9 4535.12,2689.07 4535.12,2624.13 R5.2@4500.98,2590
SDA: *1.19 *1.20 R6.2 U1.43 | length 780.5
  Top Layer w10: U1.43 4650.75,3054.96 4697.77,3054.96 4726.36,3026.37 v1(4726.36,2980)
  Bottom Layer w10: *1.20 *1.19 4592.67,2587.33 R6.2 4589.02,2590 4558.71,2620.31 4558.71,2683.83 4579.88,2705 4613.66,2705 4639.56,2730.9 4639.56,2893.2 v1(4726.36,2980)
SET: U1.26 Y1.12 | length 712
  Top Layer w10: v1(4741.1,3120) 4755,3120 4812.02,3177.02 4886.15,3177.02 4898.39,3189.25 4898.39,3224.25 U1.26
  Bottom Layer w10: Y1.12 4372.52,3072.48 4420.04,3120 v1(4741.1,3120)
SWCLK: (+)SWD.3 U1.37 | length 444.2
  Top Layer w10: U1.37@4660,3175 v1(4660,3205)
  Bottom Layer w10: 4334.88,3420 4549.88,3205 v1(4660,3205)
SWDIO: (+)SWD.2 U1.34 | length 419.8
  Top Layer w10: U1.34 v1(4741.1,3280)
  Bottom Layer w10: 4434.88,3420 4574.88,3280 v1(4741.1,3280)
USART3_RX: R16.1 U1.22 | length 932.5
  Top Layer w10: v1(4830,3075) 4870.71,3075 4929.41,3133.7 4969.25,3133.7 U1.22
  Bottom Layer w10: R16.1 4150.31,3031.49 4225.66,2956.15 4356.27,2956.15 4475.12,3075 v1(4830,3075)
USART3_TX: R15.1 U1.21 | length 922.4
  Top Layer w10: v1(4870.47,3050.24) 4934.25,3114.02 4969.25,3114.02 U1.21
  Bottom Layer w10: R15.1 4162.72,2877.41 4317.41,2877.41 4488.17,3048.17 4868.4,3048.17 v1(4870.47,3050.24)
VDD: C6.2 C7.2 C8.2 C9.2 R7.1 U1.1 U1.24 U1.36 U1.48 | length 1378.8
  Top Layer w10: 4559.53,2956.73 U1.48 ; 4625,3250 4654.84,3250 4701.26,3250 4701.73,3249.53 U1.36
  Top Layer w15: R7.1 4373.48,3088.95 4517.19,3088.95 ; U1.1@4699.74,2905.36 4610.9,2905.36 4559.53,2956.73 4550,2966.26 C6.2 4550,3056.14 4517.19,3088.95 ; U1.24@4970,3175.26 4970,3284.45 4909.76,3344.68 C9.2 C7.2 4719.69,3344.68 4625,3250 4621.82,3250 4553.77,3181.95 4553.77,3143.92 C8.2 4550,3121.76 4517.19,3088.95
VDDA: C12.2 C13.2 CiZhu1.2 U1.9 | length 308.6
  Top Layer w10: U1.9 4859.41,2905.36 4859.41,2870.35 4925.16,2804.61 4926.69,2804.61 C13.2 C13.2@4950,2791.3
  Top Layer w15: C13.2@4950,2791.3 C12.2 CiZhu1.2
pads on no net: *1. *1.7 S.3 S.4 S.5 S.18 S.19 S.20 S.21 SW1. SW1.7 SW1.8 SW1.9 SW1.10 SW1.c SW1.d U1.2 U1.3 U1.4 U1.10 U1.14 U1.15 U1.16 U1.17 U1.18 U1.19 U1.27 U1.28 U1.29 U1.30 U1.31 U1.32 U1.33 U1.38 U1.39 U1.40 U1.41 U1.45 U1.46 U2.4 U3.2 U3.5 U4.2 U4.5 X1.2 X1.4 Y1.1 Y1.2 Y1.3 Y1.4 Y1.5 Y1.6 Y1.7 Y1.8

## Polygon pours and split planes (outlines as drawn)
GND on Top Layer (solid, remove dead copper, pour order 42): 3690,3585 3700,3575 6160,3575 6160,2285 5980,2105 5915,2170 3700,2170
GND on Bottom Layer (solid, remove dead copper, pour order 44): 3720,3605 6105,3605 6200,3510 6100,3410 6100,2215 3825,2215 3740,2300

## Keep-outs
Keep-Out Layer:
  lines w10: 3870,3417.36 3870,2393.74 ccw(c3948.74,2393.74) 3948.74,2315 5917.24,2315 ccw(c5917.24,2393.74) 5995.98,2393.74 5995.98,3417.36 ccw(c5917.24,3417.36) 5917.24,3496.1 3948.74,3496.1

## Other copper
Top Layer:
  pour cut-out: 5137.95,3304.06 4794.16,3304.06 4794.16,2767.54 4800.32,2761.37 5142.28,2761.37
Bottom Layer:
  pour cut-out: 5141.73,3305 4800,3305 4800,2763.43 5141.73,2763.43

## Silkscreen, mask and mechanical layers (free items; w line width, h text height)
Mechanical 1:
  lines w10: 3870,3417.36 cw(c3948.74,3417.36) 3948.74,3496.1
